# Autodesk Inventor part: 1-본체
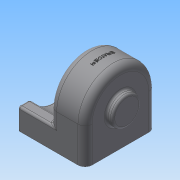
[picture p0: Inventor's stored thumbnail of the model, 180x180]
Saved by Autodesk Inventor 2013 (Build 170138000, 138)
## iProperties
Created: 2015-02
Part Number: 1-본체
Material: 일반
Document SubType Name: Modeling
Designer: Administrator
Density: 1 g/cm^3
Author: Administrator
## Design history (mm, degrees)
sketch "스케치1"
  geometry: L1 (47.5, -50)-(-47.5, -50); L2 (-47.5, -50)-(-47.5, 50); L3 (-47.5, 50)-(47.5, 50); L4 (47.5, 50)-(47.5, -50); L5 (47.5, -50)-(-47.5, 50); L6 (-47.5, -50)-(47.5, 50); 1 further point
  constraints: 12 end point, 2 midpoint, 2 parallel, 1 horizontal, 1 perpendicular
  dimensions: "d0" = 95 distance of L2.end L3.end; "d2" = 100 distance of L1.end L2.end
extrude "돌출1" new body sketch "스케치1" distance "d3" = 30; taper "d4" = 0 deg
sketch "스케치2"
  geometry: L1 (0, 100)-(0, 0) reference; L2 (0, 100)-(-30, 100) reference; L3 (-30, 0)-(-30, 100) reference; L4 (0, 0)-(-30, 0) reference; L5 (-50, 100)-(0, 100); L6 (0, 0)-(-50, 0); L7 (0, 0)-(0, 100); A1 r 50 centre (-50, 50) between (-50, 100) and (-50, 0); 2 further points
  constraints: 6 end point, 2 point on circle, 2 tangent, 1 centre point, 1 horizontal alignment, 1 midpoint
  dimensions: "d5" = 100 diameter of A1; "d7" = 50 distance from line of L1 A1.centre
extrude "돌출2" join sketch "스케치2" distance "d8" = 50; taper "d9" = 0 deg
sketch "스케치3"
  geometry: C1 r 40 at (50, 50); A1 r 50 centre (50, 50) between (50, 0) and (50, 100) reference; 1 further point
  constraints: 1 centre point, 1 coincident
  dimensions: "d10" = 80 diameter of C1
extrude "돌출3" cut sketch "스케치3" stored distance "d13" = 50; taper "d14" = 0 deg
sketch "스케치4"
  geometry: C1 r 25 at (50, 50); A1 r 40 centre (50, 50) between (30, 84.641) and (30, 15.359) reference; 1 further point
  constraints: 1 centre point, 1 coincident
  dimensions: "d15" = 50 diameter of C1
extrude "돌출4" join sketch "스케치4" distance "d17" = 10; taper "d18" = -20 deg
sketch "스케치5"
  geometry: C1 r 20 at (-50, 50); A1 r 50 centre (-50, 50) between (-50, 100) and (-50, 0) reference; 1 further point
  constraints: 1 centre point, 1 coincident
  dimensions: "d19" = 40 diameter of C1
extrude "돌출5" join sketch "스케치5" distance "d21" = 9; taper "d22" = 0 deg
node "작업 평면1"
sketch "스케치6"
  geometry: L1 (50, 100)-(30, 100) reference; L2 (0, 100)-(30, 100) reference; L3 (30, 0)-(50, 0) reference; L4 (0, 0)-(30, 0) reference; L5 (0, 96)-(30, 96); L6 (30, 96)-(50, 96); L7 (50, 4)-(30, 4); L8 (30, 4)-(0, 4); L9 (0, 96)-(0, 4); L10 (0, 0)-(0, 100) reference; A1 r 50 centre (50, 50) between (50, 0) and (50, 100) reference; A2 r 46 centre (50, 50) between (50, 4) and (50, 96); 2 further points
  constraints: 10 end point, 2 point on circle, 1 centre point, 1 midpoint, 1 perpendicular, 1 vertical alignment, 4 other
  dimensions: "d24" = 4 radial gap between concentric circles of A1 A2
extrude "돌출6" cut sketch "스케치6" distance "d25" = 42; taper "d26" = 0 deg
hole "구멍1" diameter "d29" = 20; stored, may be unused: countersink angle "d33" = 90 deg, drill point angle "d35" = 0 deg; dims "d30" = 6, "d31" = 28, "d32" = 10, "d34" = 14, "d45" = 10, "d46" = 10
hole "구멍2" diameter "d38" = 20; stored, may be unused: countersink angle "d42" = 90 deg, drill point angle "d44" = 0 deg; dims "d36" = 10, "d37" = 10, "d39" = 6, "d40" = 28, "d41" = 8, "d43" = 10
sketch "스케치7"
  geometry: C1 r 14 at (0, 0) reference; C2 r 21.36 at (0, 0) reference; A1 r 18 centre (0, 0) between (-18, 0) and (18, 0); 3 further points
  constraints: 4 point on circle, 2 horizontal alignment, 2 vertical alignment, 1 centre point, 1 coincident
  dimensions: "d47" = 36 diameter of A1
hole "구멍3" sketch "스케치7" at (-18, 0), (18, 0), (0, 18), (0, -18) diameter "d49" = 2.459; stored, may be unused: countersink angle "d53" = 90 deg, drill point angle "d55" = 118 deg; dims "d50" = 6, "d51" = 28, "d52" = 8, "d54" = 9
sketch "스케치8"
  geometry: L1 (47.5, -50)-(47.5, 50) reference; L2 (38.5, -41.75)-(5.5, -41.75); L3 (5.5, -41.75)-(5.5, 41.75); L4 (5.5, 41.75)-(38.5, 41.75); L5 (38.5, 41.75)-(38.5, -41.75); L6 (38.5, -41.75)-(5.5, 41.75); L7 (5.5, -41.75)-(38.5, 41.75); 7 further points
  constraints: 12 end point, 4 coincident, 3 midpoint, 2 parallel, 1 horizontal, 1 horizontal alignment, 1 perpendicular
  dimensions: "d56" = 33 distance of L3.end L4.end; "d58" = 9 distance between parallel lines of L1 L5; "d59" = 83.5 distance of L4.end L2.start
hole "구멍4" sketch "스케치8" at (5.5, 41.75), (38.5, 41.75), (38.5, -41.75), (5.5, -41.75) diameter "d60" = 5.134; stored, may be unused: countersink angle "d64" = 90 deg, drill point angle "d66" = 118 deg; dims "d61" = 10, "d62" = 28, "d63" = 8, "d65" = 13
fillet "모깎기1" dims "d67" = 10, "d68" = 6, "d69" = 0.3, "d70" = 3
fillet "모깎기2" dims "d71" = 3
chamfer "모따기1" distance "d72" = 1; stored, may be unused: second distance "d73" = 2, angle "d74" = 45 deg
node "작업 평면2"
sketch "스케치9"
  geometry: L1 (0, 40)-(0, -40) reference; 2 further points
  constraints: 1 horizontal alignment, 1 other
  dimensions: "d75" = 25 distance from line of L1 point (-25, 0)
feature "엠보싱1" sketch "스케치9" dims "d76" = 0.5, "d77" = 0
node "솔리드1"
other parameters: "d23" = -4
